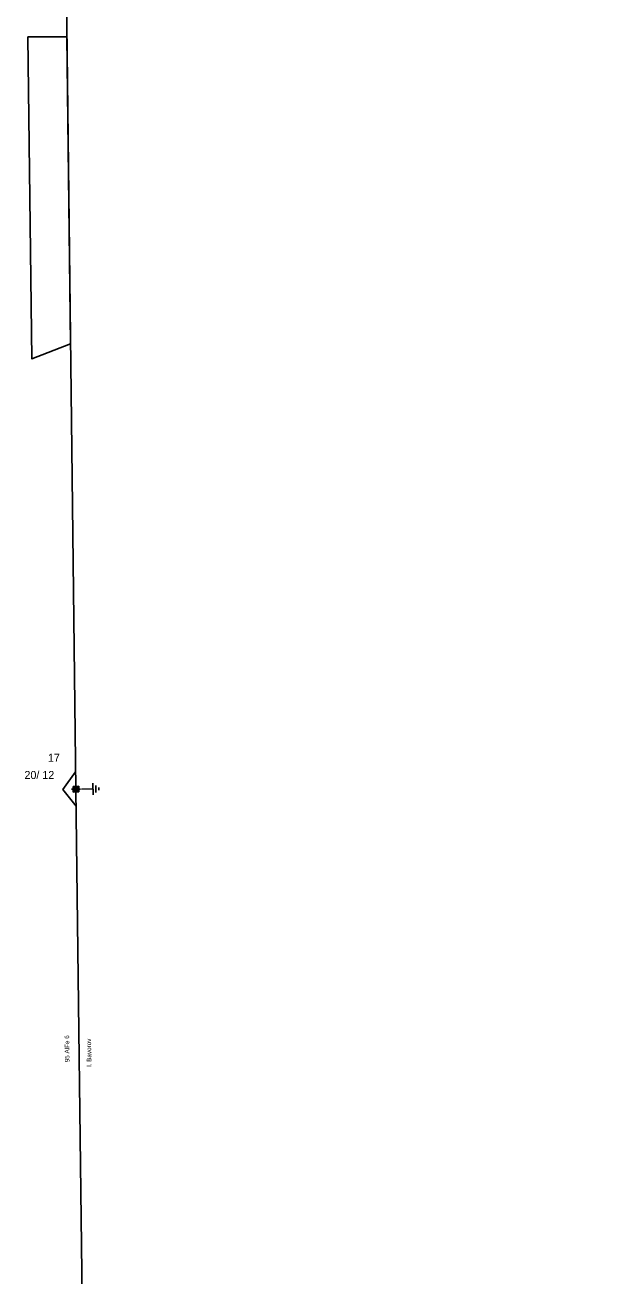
# Model space of a CAD drawing. Extents: x -788491 to -785797, y -1154753 to -1152002.
# Drawn here: x -786709.8 to -786582.7, y -1152523.6 to -1152250.1 of the extents above; entities that cross this region are included whole.
import ezdxf

# ---------------------------------------------------------------- set-up
doc = ezdxf.new("R2010")
doc.units = 0
for name, color, linetype in [('Vrstva 1', 7, 'Continuous'), ('Vrstva 13', 7, 'Continuous'), ('Vrstva 14', 7, 'Continuous'), ('Vrstva 15', 7, 'Continuous'), ('Vrstva 18', 7, 'Continuous'), ('Vrstva 2', 7, 'Continuous'), ('Vrstva 3', 7, 'Continuous'), ('Vrstva 35', 7, 'Continuous'), ('Vrstva 49', 7, 'Continuous')]:
    doc.layers.add(name, color=color, linetype=linetype)

# ---------------------------------------------------------------- blocks, each defined once
blk = doc.blocks.new('VN860')
at = {"layer": 'Vrstva 15'}
for points in [[(-3.74, 0), (0.01, 2.82)], [(0.01, 2.82), (3.76, 0)]]:
    blk.add_lwpolyline(points, dxfattribs=at)
blk = doc.blocks.new('VN810')
at = {"layer": 'Vrstva 14'}
for points in [[(0, -1.25), (0, -3.75)], [(1.25, -3.75), (-1.25, -3.75)], [(0.77, -4.37), (-0.8, -4.37)], [(0, -5), (-0.25, -5)], [(0.27, -5), (0, -5)]]:
    blk.add_lwpolyline(points, dxfattribs=at)
blk = doc.blocks.new('VN470')
at = {"layer": 'Vrstva 2'}
for points in [[(-1.23, 1.22), (1.23, 1.22)], [(-1.23, -1.23), (-1.23, 1.22)], [(-0.92, 0.9), (0.92, 0.9)], [(-0.92, -0.95), (-0.92, 0.9)], [(-0.61, 0.61), (0.61, 0.61)], [(-0.61, -0.62), (-0.61, 0.61)], [(-0.31, -0.27), (-0.31, 0.34)], [(-0.31, 0.34), (0.31, 0.34)], [(0, 1.22), (0, 1.97)], [(0.31, 0.34), (0.31, -0.27)], [(0.61, 0.61), (0.61, -0.62)], [(0.92, 0.9), (0.92, -0.95)], [(1.23, 1.22), (1.23, -1.23)], [(1.23, -1.23), (-1.23, -1.23)], [(0.92, -0.95), (-0.92, -0.95)], [(0.61, -0.62), (-0.61, -0.62)], [(0.31, -0.27), (-0.31, -0.27)], [(0, -1.23), (0, -1.98)]]:
    blk.add_lwpolyline(points, dxfattribs=at)

msp = doc.modelspace()

# ---------------------------------------------------------------- linework, layer by layer
at = {"layer": 'Vrstva 1'}
msp.add_lwpolyline([(-786582.66, -1152002.36), (-786624.98, -1152053.08), (-786701.81, -1152145.29), (-786700.8, -1152243.72), (-786698.72, -1152417.16), (-786697.17, -1152540.35)], dxfattribs=at)
at = {"layer": 'Vrstva 35'}
msp.add_lwpolyline([(-786699.89, -1152319.78), (-786708.35, -1152323.08), (-786709.19, -1152252.68), (-786700.7, -1152252.68)], close=True, dxfattribs=at)

# ---------------------------------------------------------------- block references
at = {"layer": 'Vrstva 13', "xscale": 0.49999999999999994, "yscale": 0.49999999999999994, "rotation": 90.90310280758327}
msp.add_blockref('VN470', (-786698.72, -1152417.16), dxfattribs=at)
at = {"layer": 'Vrstva 15', "rotation": 90.7625416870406}
msp.add_blockref('VN810', (-786698.72, -1152417.16), dxfattribs=at)
at = {"layer": 'Vrstva 18', "rotation": 90.90835273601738}
msp.add_blockref('VN860', (-786698.72, -1152417.16), dxfattribs=at)

# ---------------------------------------------------------------- texts
at = {"layer": 'Vrstva 14'}
msp.add_text('17', height=1.75, dxfattribs=at).set_placement((-786704.83, -1152411.16))
at = {"layer": 'Vrstva 2'}
msp.add_text('95 AlFe 6', height=1, rotation=90.721, dxfattribs=at).set_placement((-786700.12, -1152476.87))
at = {"layer": 'Vrstva 3'}
msp.add_text('l. Bavorov', height=1, rotation=90.721, dxfattribs=at).set_placement((-786695.33, -1152477.83))
at = {"layer": 'Vrstva 49'}
msp.add_text('20/ 12', height=1.75, dxfattribs=at).set_placement((-786709.96, -1152414.93))

doc.saveas('drawing.dxf')
